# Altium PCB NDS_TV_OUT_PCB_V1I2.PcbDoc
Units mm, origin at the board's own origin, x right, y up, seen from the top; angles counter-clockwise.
Board outline 38 x 49 mm, 4 copper layers (L1, L2-GND, L3-PW, L4), stack 0.603 mm thick; 44 components, 33 nets, 151 pads, 52 vias.
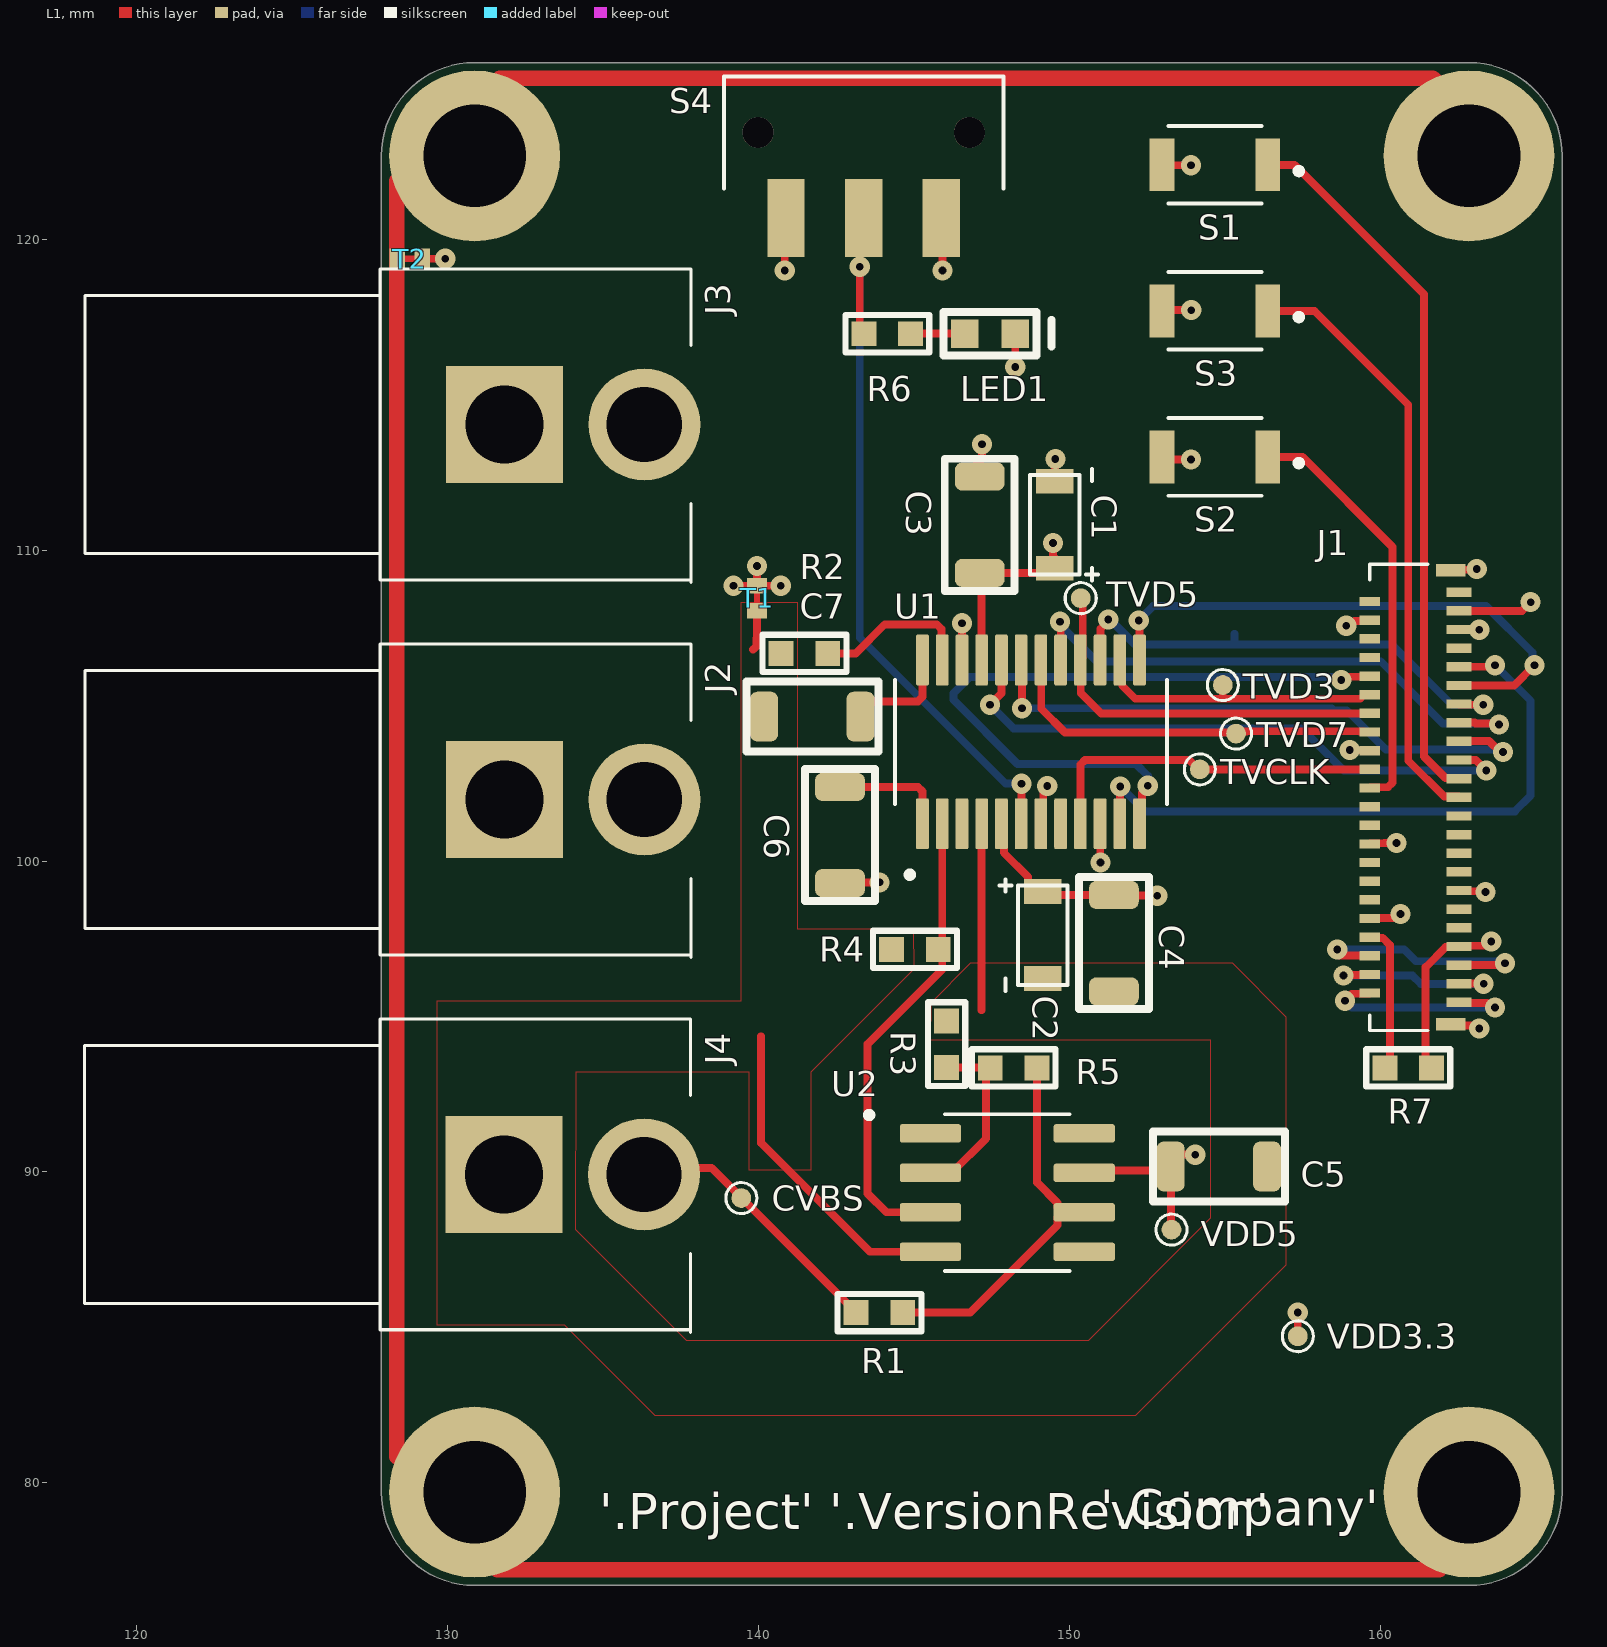
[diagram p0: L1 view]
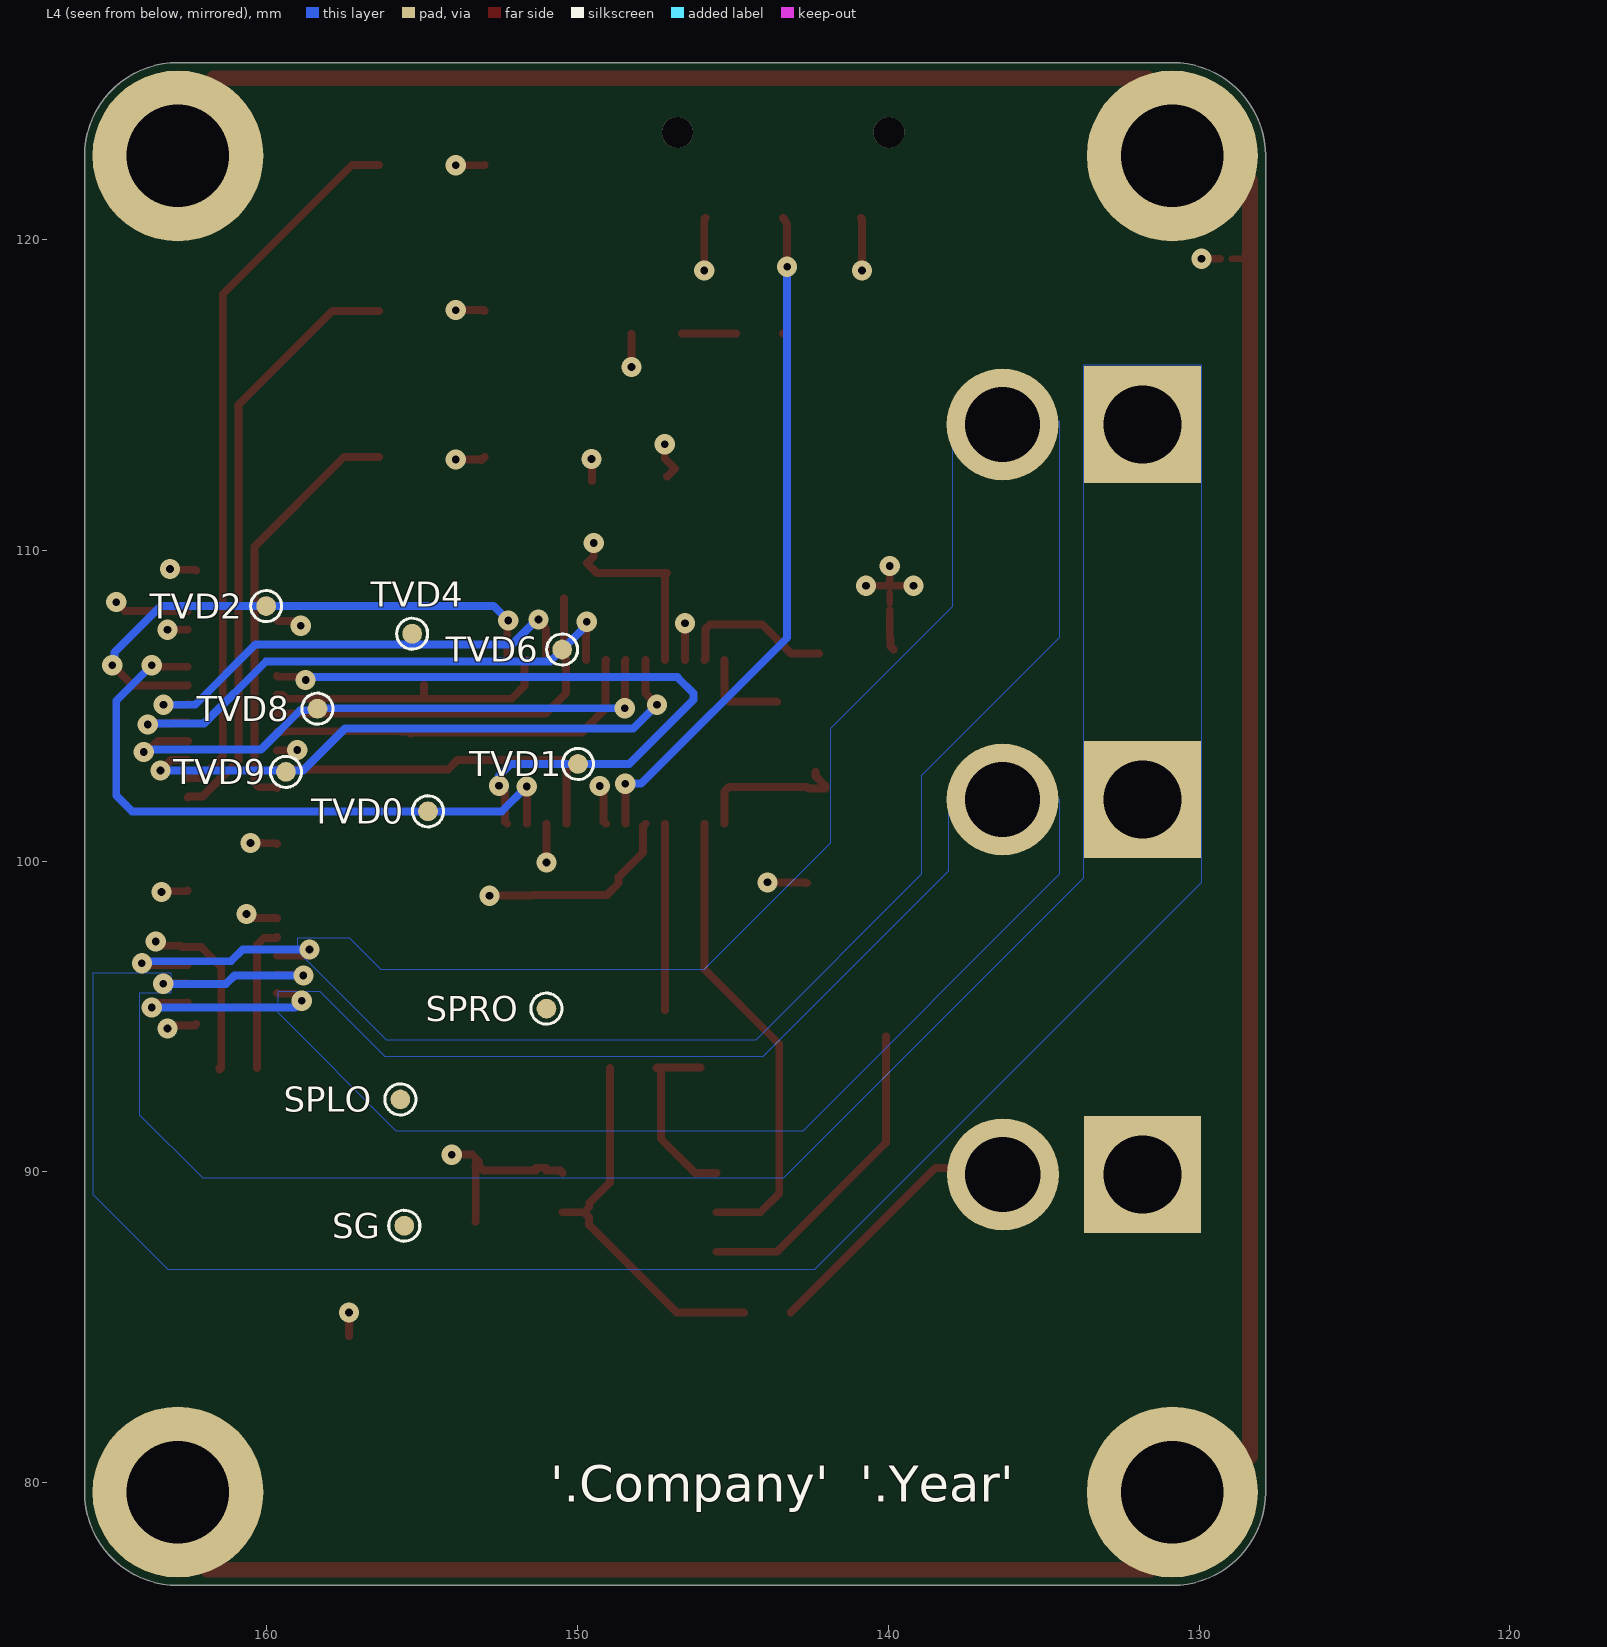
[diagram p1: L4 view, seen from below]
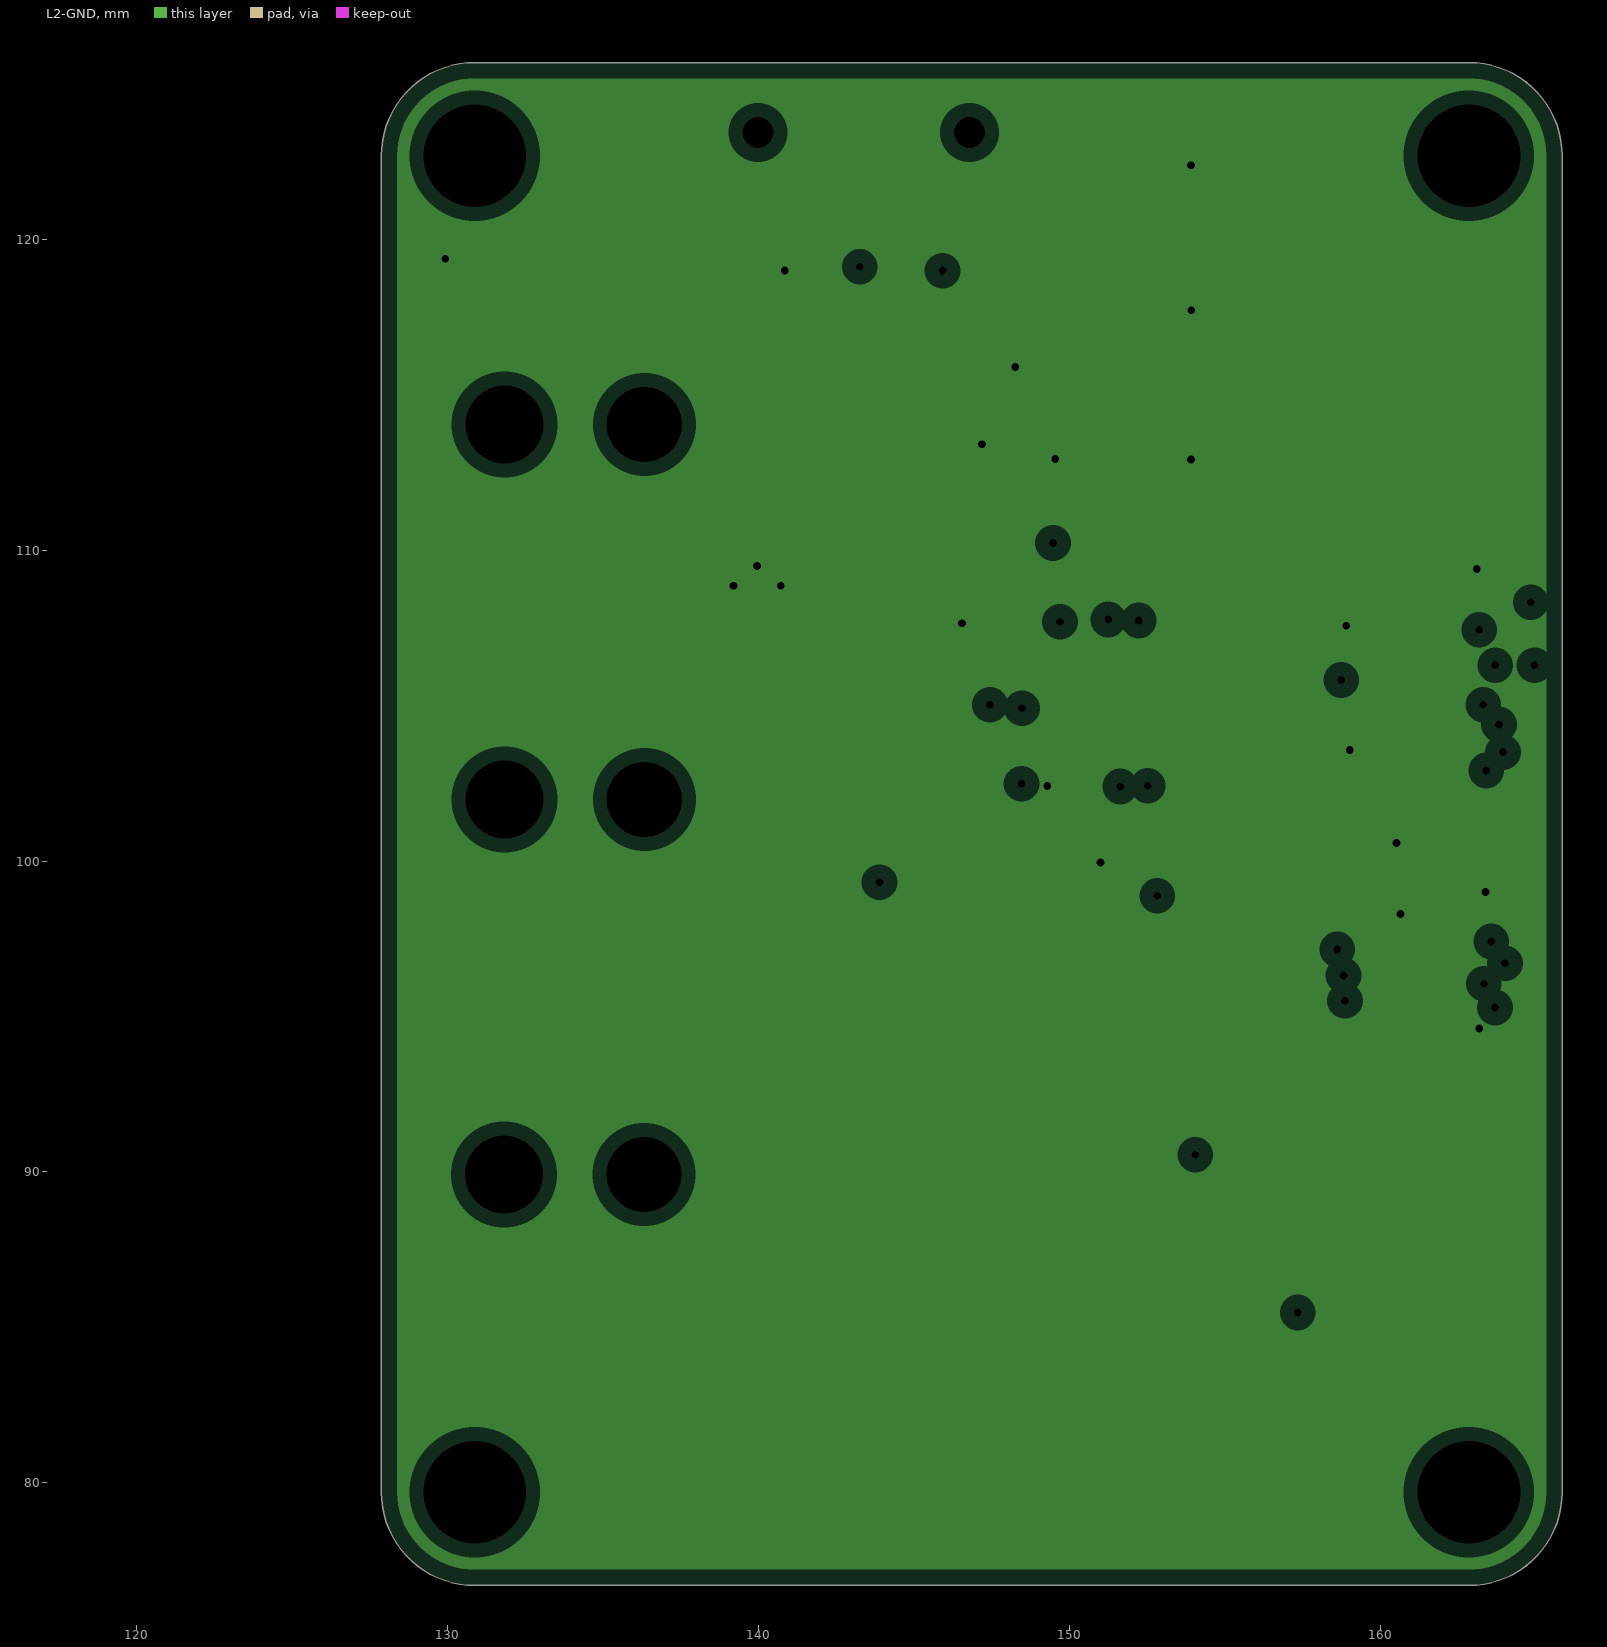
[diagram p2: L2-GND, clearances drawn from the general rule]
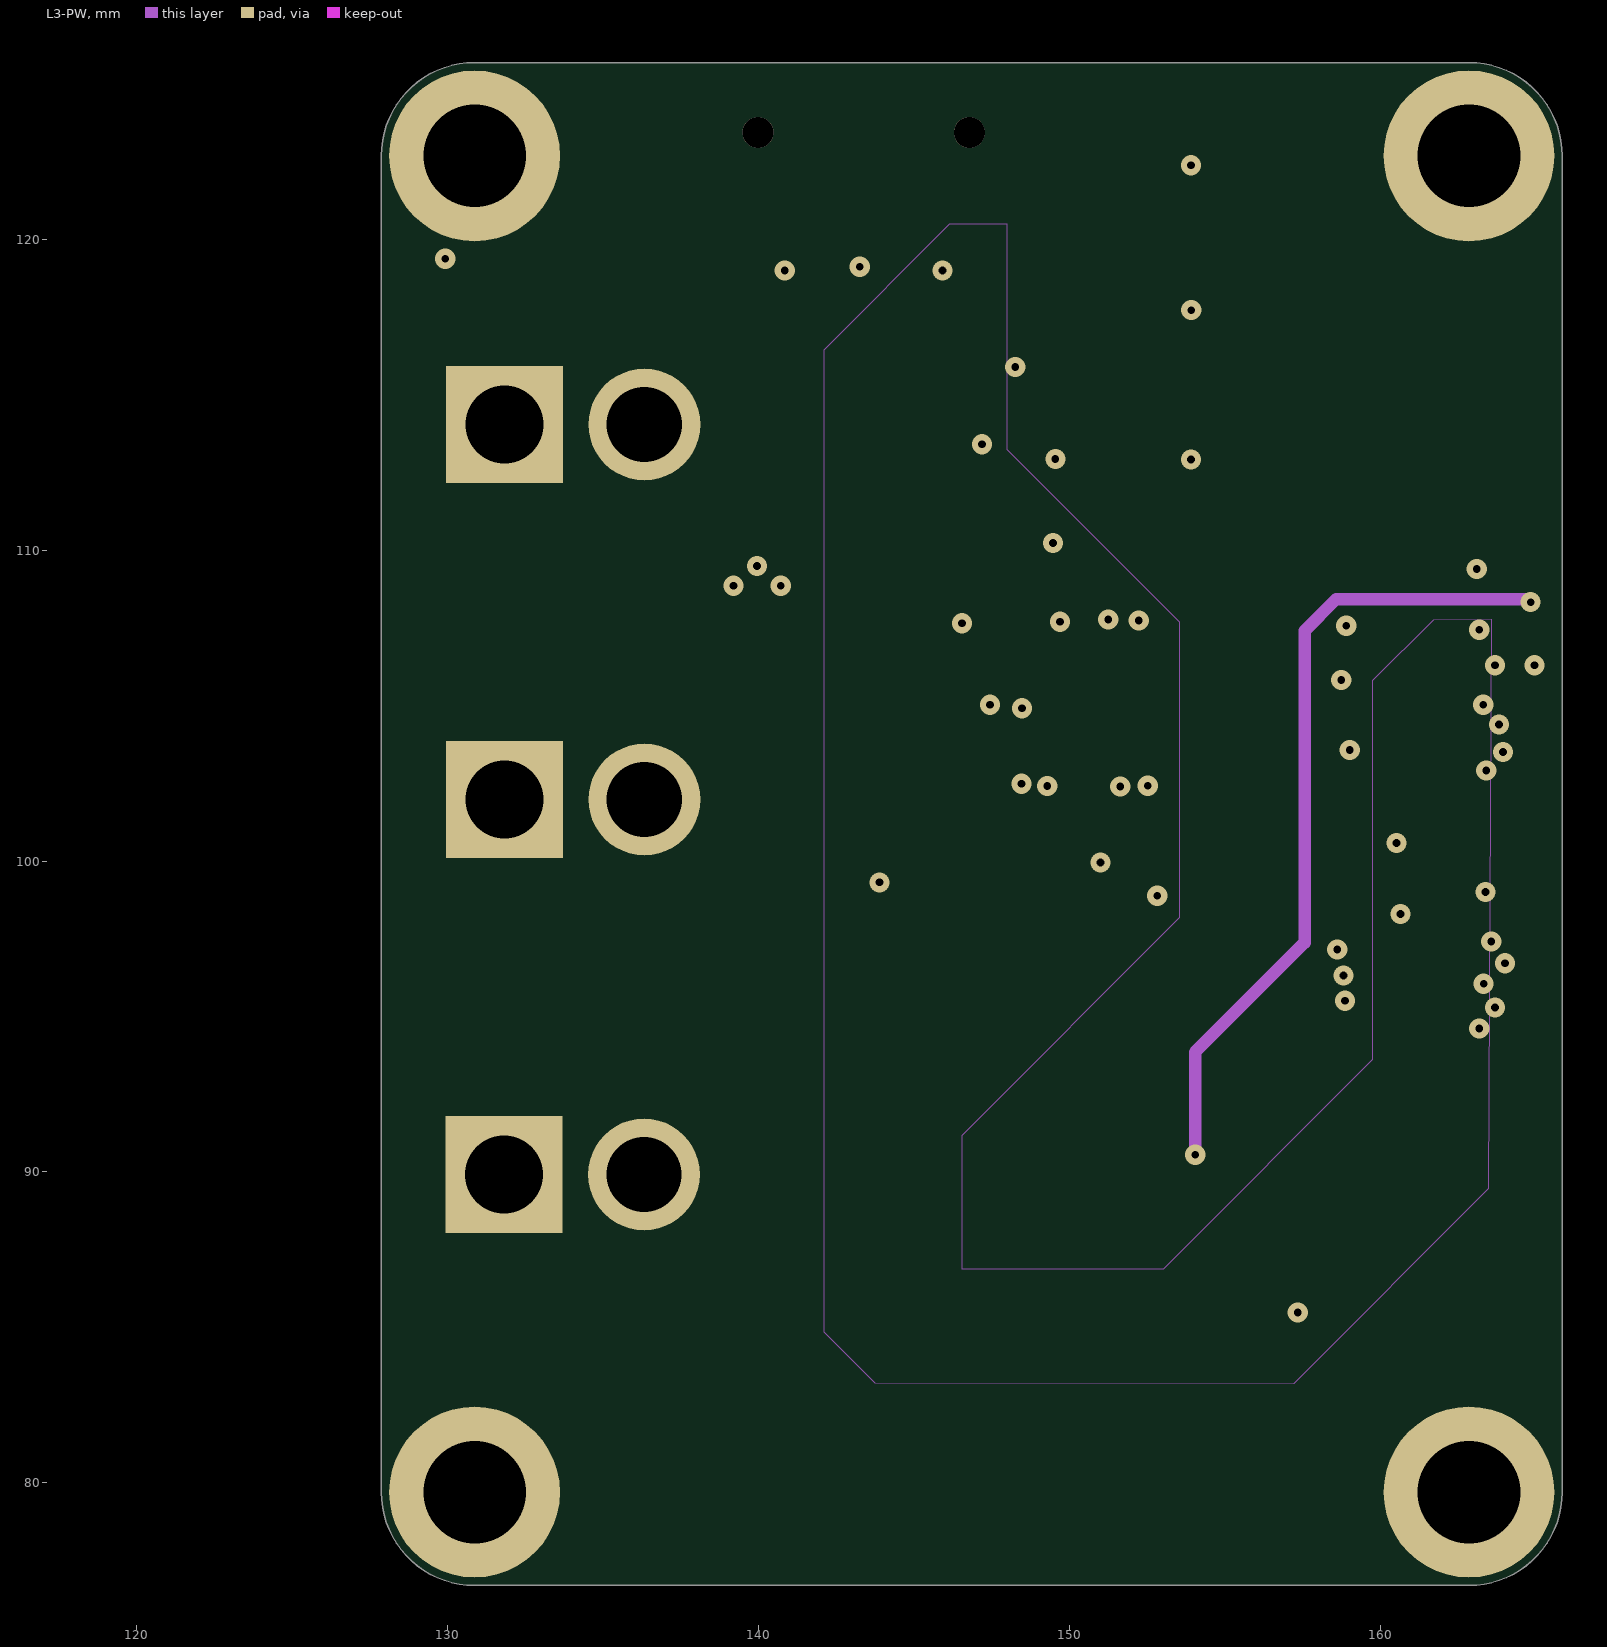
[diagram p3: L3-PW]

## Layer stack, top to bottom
Top Solder: solder mask 0.0102, Solder Resist, Dk 3.5
L1: signal copper 0.0356
Dielectric 1: prepreg 0.0711, PP-006, Dk 4.1
L2-GND: plane copper 0.035, net GND
Dielectric1: dielectric 0.32, FR-4, Dk 4.8
L3-PW: signal copper 0.035
Dielectric 2: prepreg 0.0711, PP-006, Dk 4.1
L4: signal copper 0.0356
Bottom Solder: solder mask 0.0102, Solder Resist, Dk 3.5

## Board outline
127.862,79.692 ccw(c130.862,79.692) 130.862,76.692 162.862,76.692 ccw(c162.862,79.692) 165.862,79.692 165.862,122.692 ccw(c162.862,122.692) 162.862,125.692 130.862,125.692 ccw(c130.862,122.692) 127.862,122.692

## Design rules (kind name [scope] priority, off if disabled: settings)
AssemblyTestPointUsage [All] p0: scope1count=1 scope1_0_kind=Board scope1_0_value=Board scope2count=1 scope2_0_kind=Board scope2_0_value=Board commentlength=0
AssemblyTestpoint [All] p0: scope1count=1 scope1_0_kind=Board scope1_0_value=Board scope2count=1 scope2_0_kind=Board scope2_0_value=Board commentlength=0
BoardOutlineClearance [All] p0: scope1count=1 scope1_0_kind=Board scope1_0_value=Board scope2count=1 scope2_0_kind=Board scope2_0_value=Board commentlength=0 gap=0.25
BoardOutlineClearance [All] p1: gap=0.25 ignorepadtopadclearanceinfootprint=FALSE except(0: Arc-SplitContinuation Track-SplitContinuation SMDPad-SplitContinuation THPad-SplitContinuation Via-SplitContinuation Fill-SplitContinuation Poly-SplitContinuation Region-SplitContinuation Text-SplitContinuation)
Clearance Clearance-xPP-xTP-xTT [All] p0: scope1count=1 scope1_0_kind=Board scope1_0_value=Board scope2count=1 scope2_0_kind=Board scope2_0_value=Board commentlength=0 gap=0.15
Clearance "Clearance poly Power Polygon" [All] p0 off: scope1count=1 scope1_0_kind=Layer scope1_0_value=TOP scope2count=1 scope2_0_kind=Board scope2_0_value=Board commentlength=48 gap=0.4 // Protel DXP Scope 2 Expression Was: InPolygon
Clearance "Clearance poly Power Polygon" [OnLayer('L4-PWR') vs InPolygon] p1: gap=0.4 ignorepadtopadclearanceinfootprint=FALSE
Clearance Clearance-xPP-xTP-xTT [All] p2: gap=0.15 ignorepadtopadclearanceinfootprint=FALSE
ComponentClearance [All] p0: scope1count=1 scope1_0_kind=Board scope1_0_value=Board scope2count=1 scope2_0_kind=Board scope2_0_value=Board commentlength=0 gap=0 collisioncheckmode=3
ComponentClearance [All] p1: gap=0 collisioncheckmode=3 verticalgap=0 showdistances=FALSE
DiffPairsRouting DiffPairsRoutingGBE [All] p0 off: scope1count=1 scope1_0_kind=Board scope1_0_value=Board scope2count=1 scope2_0_kind=Board scope2_0_value=Board commentlength=88 // Protel DXP Scope 1 Expression Was: InDifferentialPairClass('All Differential Pairs')
DiffPairsRouting DiffPairsRoutingGBE [InDifferentialPairClass('All Differential Pairs')] p1: maxlimit=0.22 minlimit=0.22 mostfreqgap=0.22 toplayer_minwidth=0.15 toplayer_maxwidth=0.15 toplayer_prefwidth=0.15 midlayer1_minwidth=0.15 midlayer1_maxwidth=0.15 midlayer1_prefwidth=0.15 bottomlayer_minwidth=0.15 bottomlayer_maxwidth=0.15 bottomlayer_prefwidth=0.15 maxuncoupledlength=1.25
FabricationTestPointUsage [All] p0: scope1count=1 scope1_0_kind=Board scope1_0_value=Board scope2count=1 scope2_0_kind=Board scope2_0_value=Board commentlength=0 valid=0 allowmultiple=FALSE
FabricationTestpoint [All] p0: scope1count=1 scope1_0_kind=Board scope1_0_value=Board scope2count=1 scope2_0_kind=Board scope2_0_value=Board commentlength=0 side=3 testpointundercomponent=TRUE minsize=1.016 maxsize=2.54 preferedsize=1.524 minholesize=0 maxholesize=1.016 preferedholesize=0.813 testpointgrid=0.025
FanoutControl Fanout_Default [All] p0: scope1count=1 scope1_0_kind=Board scope1_0_value=Board scope2count=1 scope2_0_kind=Board scope2_0_value=Board commentlength=30 // Fanout_Default (Default Rule)
FanoutControl Fanout_Small [All] p0 off: scope1count=1 scope1_0_kind=Board scope1_0_value=Board scope2count=1 scope2_0_kind=Board scope2_0_value=Board commentlength=84 // Protel DXP Scope 1 Expression Was: (CompPinCount < 5)   Fanout_Small (Default Rule)
FanoutControl Fanout_SOIC [All] p0 off: scope1count=1 scope1_0_kind=Board scope1_0_value=Board scope2count=1 scope2_0_kind=Board scope2_0_value=Board commentlength=71 // Protel DXP Scope 1 Expression Was: IsSOIC   Fanout_SOIC (Default Rule)
FanoutControl Fanout_LCC [All] p0 off: scope1count=1 scope1_0_kind=Board scope1_0_value=Board scope2count=1 scope2_0_kind=Board scope2_0_value=Board commentlength=69 // Protel DXP Scope 1 Expression Was: IsLCC   Fanout_LCC (Default Rule)
FanoutControl Fanout_BGA [All] p0 off: scope1count=1 scope1_0_kind=Board scope1_0_value=Board scope2count=1 scope2_0_kind=Board scope2_0_value=Board commentlength=69 // Protel DXP Scope 1 Expression Was: IsBGA   Fanout_BGA (Default Rule)
Height [All] p0: scope1count=1 scope1_0_kind=Board scope1_0_value=Board scope2count=1 scope2_0_kind=Board scope2_0_value=Board commentlength=0
Height [All] p1: minheight=0 maxheight=25 prefheight=12.5
HoleSize HoleSize-PTH [All] p0: scope1count=1 scope1_0_kind=Board scope1_0_value=Board scope2count=1 scope2_0_kind=Board scope2_0_value=Board commentlength=0 absolutevalues=TRUE maxlimit=4 minlimit=0.15 maxpercent=80.000 minpercent=20.000
HoleSize HoleSize-PTH [All] p1: absolutevalues=TRUE maxlimit=4 minlimit=0.15 maxpercent=80.000 minpercent=20.000
HoleToHoleClearance [All] p0: scope1count=1 scope1_0_kind=Board scope1_0_value=Board scope2count=1 scope2_0_kind=Board scope2_0_value=Board commentlength=0
HoleToHoleClearance [All] p1: gap=0.35 allowstackedmicrovias=TRUE
LayerPairs [All] p0: scope1count=1 scope1_0_kind=Board scope1_0_value=Board scope2count=1 scope2_0_kind=Board scope2_0_value=Board commentlength=0 enforce=TRUE
MatchedLengths MatchedLengths_USB2 [All] p0: scope1count=1 scope1_0_kind=NetClass scope1_0_value=USB2 scope2count=1 scope2_0_kind=Board scope2_0_value=Board commentlength=0 tolerance=0.127 amplitude=5.08 gap=0.508 style=90-Degree
MatchedLengths MatchedLengths_USB3 [All] p0: scope1count=1 scope1_0_kind=NetClass scope1_0_value=USB3 scope2count=1 scope2_0_kind=Board scope2_0_value=Board commentlength=0 tolerance=0.127 amplitude=5.08 gap=0.508 style=90-Degree
MatchedLengths MatchedLengths_USB-GBE [All] p0: scope1count=1 scope1_0_kind=NetClass scope1_0_value=USB-GBE scope2count=1 scope2_0_kind=Board scope2_0_value=Board commentlength=0 tolerance=0.127 amplitude=5.08 gap=0.508 style=90-Degree
MatchedLengths MatchedLengths_HDMI [All] p0: scope1count=1 scope1_0_kind=NetClass scope1_0_value=HDMI scope2count=1 scope2_0_kind=Board scope2_0_value=Board commentlength=0 tolerance=0.127 amplitude=5.08 gap=0.508 style=90-Degree
MatchedLengths MatchedLengths_GBE2 [All] p0: scope1count=1 scope1_0_kind=NetClass scope1_0_value=GBE2 scope2count=1 scope2_0_kind=Board scope2_0_value=Board commentlength=0 tolerance=0.127 amplitude=5.08 gap=0.508 style=90-Degree
MatchedLengths MatchedLengths_GBE1 [All] p0: scope1count=1 scope1_0_kind=NetClass scope1_0_value=GBE1 scope2count=1 scope2_0_kind=Board scope2_0_value=Board commentlength=0 tolerance=0.127 amplitude=5.08 gap=0.508 style=90-Degree
MatchedLengths MatchedLengths_GBE0 [All] p0: scope1count=1 scope1_0_kind=NetClass scope1_0_value=GBE0 scope2count=1 scope2_0_kind=Board scope2_0_value=Board commentlength=0 tolerance=0.127 amplitude=5.08 gap=0.508 style=90-Degree
MatchedLengths DiffPairClass [All] p0 off: scope1count=1 scope1_0_kind=Board scope1_0_value=Board scope2count=1 scope2_0_kind=Board scope2_0_value=Board commentlength=88 tolerance=0.127 amplitude=5.08 gap=0.508 style=90-Degree // Protel DXP Scope 1 Expression Was: InDifferentialPairClass('All Differential Pairs')
MatchedLengths MatchedLengths_USB_DiffPairs [All] p0 off: scope1count=1 scope1_0_kind=Board scope1_0_value=Board scope2count=1 scope2_0_kind=Board scope2_0_value=Board commentlength=140 tolerance=0.127 amplitude=5.08 gap=0.508 style=90-Degree // Protel DXP Scope 1 Expression Was: InxSignalClass('USB_CHJ1_1_DL') OR InxSignalClass('USB_CHJ1_1_RX') OR InxSignalClass('USB_CHJ1_1_TX')
MatchedLengths MatchedLengths_USB_DiffPairs_1 [All] p0 off: scope1count=1 scope1_0_kind=Board scope1_0_value=Board scope2count=1 scope2_0_kind=Board scope2_0_value=Board commentlength=140 tolerance=0.127 amplitude=5.08 gap=0.508 style=90-Degree // Protel DXP Scope 1 Expression Was: InxSignalClass('USB_CHJ1_1_DL') OR InxSignalClass('USB_CHJ1_1_RX') OR InxSignalClass('USB_CHJ1_1_TX')
MatchedLengths MatchedLengths_USB_DiffPairs_1 [InxSignalClass('USB_CHJ1_1_DL') OR InxSignalClass('USB_CHJ1_1_RX') OR InxSignalClass('USB_CHJ1_1_TX')] p1: tolerance=0.127 checknetsindiffpair=TRUE checkdiffpairvsdiffpair=FALSE checkxsignals=FALSE checkothers=FALSE
MatchedLengths MatchedLengths_USB_DiffPairs [InxSignalClass('USB_CHJ1_1_DL') OR InxSignalClass('USB_CHJ1_1_RX') OR InxSignalClass('USB_CHJ1_1_TX')] p2: tolerance=0.127 checknetsindiffpair=TRUE checkdiffpairvsdiffpair=FALSE checkxsignals=FALSE checkothers=FALSE
MatchedLengths DiffPairClass [InDifferentialPairClass('All Differential Pairs')] p3: tolerance=0.127 checknetsindiffpair=TRUE checkdiffpairvsdiffpair=FALSE checkxsignals=FALSE checkothers=FALSE
MatchedLengths MatchedLengths_GBE0 [InNetClass('GBE0')] p4: tolerance=0.127 checknetsindiffpair=FALSE checkdiffpairvsdiffpair=TRUE checkxsignals=TRUE checkothers=TRUE
MatchedLengths MatchedLengths_GBE1 [InNetClass('GBE1')] p5: tolerance=0.127 checknetsindiffpair=FALSE checkdiffpairvsdiffpair=TRUE checkxsignals=TRUE checkothers=TRUE
MatchedLengths MatchedLengths_GBE2 [InNetClass('GBE2')] p6: tolerance=0.127 checknetsindiffpair=FALSE checkdiffpairvsdiffpair=TRUE checkxsignals=TRUE checkothers=TRUE
MatchedLengths MatchedLengths_HDMI [InNetClass('HDMI')] p7: tolerance=0.127 checknetsindiffpair=FALSE checkdiffpairvsdiffpair=TRUE checkxsignals=TRUE checkothers=TRUE
MatchedLengths MatchedLengths_USB-GBE [InNetClass('USB-GBE')] p8: tolerance=0.127 checknetsindiffpair=FALSE checkdiffpairvsdiffpair=TRUE checkxsignals=TRUE checkothers=TRUE
MatchedLengths MatchedLengths_USB3 [InNetClass('USB3')] p9: tolerance=0.127 checknetsindiffpair=FALSE checkdiffpairvsdiffpair=TRUE checkxsignals=TRUE checkothers=TRUE
MatchedLengths MatchedLengths_USB2 [InNetClass('USB2')] p10: tolerance=0.127 checknetsindiffpair=FALSE checkdiffpairvsdiffpair=TRUE checkxsignals=TRUE checkothers=TRUE
MinimumAnnularRing "Minimum IAR <=0.45mm" [All] p0 off: scope1count=1 scope1_0_kind=Board scope1_0_value=Board scope2count=1 scope2_0_kind=Board scope2_0_value=Board commentlength=209 minimumring=0.175 // Protel DXP Scope 1 Expression Was: ((ObjectKind = 'Pad') OR (ObjectKind = 'Via')) And (Layer = 'MultiLayer') And (HoleDiameter <= AsMM(0.45))   minimum inner annular ring for pads <= 0.45mm finished hole size
MinimumAnnularRing "Minimum IAR  >0.45mm" [All] p0 off: scope1count=1 scope1_0_kind=Board scope1_0_value=Board scope2count=1 scope2_0_kind=Board scope2_0_value=Board commentlength=207 minimumring=0.175 // Protel DXP Scope 1 Expression Was: ((ObjectKind = 'Pad') OR (ObjectKind = 'Via')) And (Layer = 'MultiLayer') And (HoleDiameter > AsMM(0.45))   minimum inner annular ring for pads > 0.45mm finished hole size
MinimumAnnularRing "Minimum IAR  >0.45mm" [((ObjectKind = 'Pad') OR (ObjectKind = 'Via')) And (Layer = 'MultiLayer') And (HoleDiameter > AsMM(0.45))] p1: minimumring=0.175 // minimum inner annular ring for pads > 0.45mm finished hole size
MinimumAnnularRing "Minimum IAR <=0.45mm" [((ObjectKind = 'Pad') OR (ObjectKind = 'Via')) And (Layer = 'MultiLayer') And (HoleDiameter <= AsMM(0.45))] p2: minimumring=0.175 // minimum inner annular ring for pads <= 0.45mm finished hole size
MinimumSolderMaskSliver [All] p0: scope1count=1 scope1_0_kind=Board scope1_0_value=Board scope2count=1 scope2_0_kind=Board scope2_0_value=Board commentlength=0
MinimumSolderMaskSliver [All] p1: minsoldermaskwidth=0.08
NetAntennae [All] p0: scope1count=1 scope1_0_kind=Board scope1_0_value=Board scope2count=1 scope2_0_kind=Board scope2_0_value=Board commentlength=0
PasteMaskExpansion [All] p0: scope1count=1 scope1_0_kind=Board scope1_0_value=Board scope2count=1 scope2_0_kind=Board scope2_0_value=Board commentlength=0 expansion=0
PlaneClearance PlaneClearance-IPI [All] p0: scope1count=1 scope1_0_kind=Board scope1_0_value=Board scope2count=1 scope2_0_kind=Board scope2_0_value=Board commentlength=0 clearance=0.45
PlaneClearance PlaneClearance-IPI [All] p1: clearance=0.45
PlaneConnect [All] p0: scope1count=1 scope1_0_kind=Board scope1_0_value=Board scope2count=1 scope2_0_kind=Board scope2_0_value=Board commentlength=0 planeconnectstyle=Relief reliefexpansion=0.2 reliefentries=4 reliefconductorwidth=0.25 reliefairgap=0.2
PlaneConnect PlaneConnect_VIA [All] p0 off: scope1count=1 scope1_0_kind=Board scope1_0_value=Board scope2count=1 scope2_0_kind=Board scope2_0_value=Board commentlength=44 planeconnectstyle=Direct reliefexpansion=0.175 reliefentries=4 reliefconductorwidth=0.2 reliefairgap=0.2 // Protel DXP Scope 1 Expression Was: IsVia
PlaneConnect PlaneConnect_PWR [All] p0: scope1count=1 scope1_0_kind=NetClass scope1_0_value=PWR scope2count=1 scope2_0_kind=Board scope2_0_value=Board commentlength=0 planeconnectstyle=Direct reliefexpansion=0.175 reliefentries=2 reliefconductorwidth=0.2 reliefairgap=0.2
PlaneConnect PlaneConnect_PWR [InNetClass('PWR')] p1: planeconnectstyle=Direct reliefexpansion=0.175 reliefentries=2 reliefconductorwidth=0.2 reliefairgap=0.2
PlaneConnect PlaneConnect_VIA [IsVia] p2: planeconnectstyle=Direct reliefexpansion=0.175 reliefentries=4 reliefconductorwidth=0.2 reliefairgap=0.2
PlaneConnect [All] p3: planeconnectstyle=Relief reliefexpansion=0.2 reliefentries=4 reliefconductorwidth=0.25 reliefairgap=0.2
PolygonConnect PolygonConnect_VIA_1 [All] p0: scope1count=1 scope1_0_kind=Board scope1_0_value=Board scope2count=1 scope2_0_kind=Board scope2_0_value=Board commentlength=0 connectstyle=Direct reliefconductorwidth=0.2 reliefentries=4 polygonreliefangle="90 Angle"
PolygonConnect PolygonConnect_SMD [All] p0 off: scope1count=1 scope1_0_kind=Board scope1_0_value=Board scope2count=1 scope2_0_kind=Board scope2_0_value=Board commentlength=84 connectstyle=Direct reliefconductorwidth=0.2 reliefentries=4 polygonreliefangle="90 Angle" // Protel DXP Scope 1 Expression Was: Not HasFootprint('NET_TIE') and InNet('AGND')
PolygonConnect [All] p0: scope1count=1 scope1_0_kind=Board scope1_0_value=Board scope2count=1 scope2_0_kind=Board scope2_0_value=Board commentlength=0 connectstyle=Relief reliefconductorwidth=0.25 reliefentries=4 polygonreliefangle="90 Angle"
PolygonConnect PolygonConnect_VIA [All] p0: scope1count=1 scope1_0_kind=Footprint scope1_0_value=NET_TIE scope2count=1 scope2_0_kind=Board scope2_0_value=Board commentlength=0 connectstyle=Direct reliefconductorwidth=0.2 reliefentries=4 polygonreliefangle="90 Angle"
PolygonConnect PolygonConnect_VIA [HasFootprint('NET_TIE')] p1: connectstyle=Direct reliefconductorwidth=0.2 reliefentries=4 polygonreliefangle="90 Angle" airgapwidth=0.2
PolygonConnect PolygonConnect_SMD [Not HasFootprint('NET_TIE') and InNet('AGND')] p2: thpad.connectstyle=Direct thpad.reliefconductorwidth=0.2 thpad.reliefentries=4 thpad.polygonreliefangle="90 Angle" thpad.airgapwidth=0.2 smdpad.connectstyle=Relief smdpad.reliefconductorwidth=0.2 smdpad.reliefentries=4 smdpad.polygonreliefangle="90 Angle" smdpad.airgapwidth=0.2 via.connectstyle=Direct via.reliefconductorwidth=0.2 via.reliefentries=4 via.polygonreliefangle="90 Angle" via.airgapwidth=0.2
PolygonConnect PolygonConnect_VIA_1 [All] p3: connectstyle=Direct reliefconductorwidth=0.2 reliefentries=4 polygonreliefangle="90 Angle" airgapwidth=0.2
PolygonConnect [All] p4: connectstyle=Relief reliefconductorwidth=0.25 reliefentries=4 polygonreliefangle="90 Angle" airgapwidth=0.2
RoutingCorners [All] p0: scope1count=1 scope1_0_kind=Board scope1_0_value=Board scope2count=1 scope2_0_kind=Board scope2_0_value=Board commentlength=0 cornerstyle=45-Degree minsetback=2.5 maxsetback=2.5
RoutingCorners [All] p1: cornerstyle=45-Degree minsetback=2.5 maxsetback=2.5
RoutingLayers [All] p0: scope1count=1 scope1_0_kind=Board scope1_0_value=Board scope2count=1 scope2_0_kind=Board scope2_0_value=Board commentlength=0 top layer=Automatic mid layer 1=Automatic bottom layer=Automatic
RoutingPriority [All] p0: scope1count=1 scope1_0_kind=Board scope1_0_value=Board scope2count=1 scope2_0_kind=Board scope2_0_value=Board commentlength=0
RoutingTopology [All] p0: scope1count=1 scope1_0_kind=Board scope1_0_value=Board scope2count=1 scope2_0_kind=Board scope2_0_value=Board commentlength=0 topology=Shortest
RoutingVias "RoutingVias <= 0.45mm" [All] p0 off: scope1count=1 scope1_0_kind=Board scope1_0_value=Board scope2count=1 scope2_0_kind=Board scope2_0_value=Board commentlength=120 holewidth=0.2 width=0.55 viastyle="Through Hole" minholewidth=0.15 minwidth=0.5 maxholewidth=0.45 maxwidth=0.8 // Protel DXP Scope 1 Expression Was: (ObjectKind = 'Via') And (HoleDiameter <= AsMM(0.45))   finishet hole size <= 0.45mm
RoutingVias "RoutingVias > 0.45mm" [All] p0 off: scope1count=1 scope1_0_kind=Board scope1_0_value=Board scope2count=1 scope2_0_kind=Board scope2_0_value=Board commentlength=118 holewidth=0.5 width=0.85 viastyle="Through Hole" minholewidth=0.5 minwidth=0.85 maxholewidth=0.9 maxwidth=1.25 // Protel DXP Scope 1 Expression Was: (ObjectKind = 'Via') And (HoleDiameter > AsMM(0.45))   finishet hole size > 0.45mm
RoutingVias "RoutingVias > 0.45mm" [(ObjectKind = 'Via') And (HoleDiameter > AsMM(0.45))] p1: holewidth=0.5 width=0.85 viastyle="Through Hole" minholewidth=0.5 minwidth=0.85 maxholewidth=0.9 maxwidth=1.25 // finishet hole size > 0.45mm
RoutingVias "RoutingVias <= 0.45mm" [(ObjectKind = 'Via') And (HoleDiameter <= AsMM(0.45))] p2: holewidth=0.2 width=0.55 viastyle="Through Hole" minholewidth=0.15 minwidth=0.5 maxholewidth=0.45 maxwidth=0.8 // finishet hole size <= 0.45mm
ShortCircuit [All] p0: scope1count=1 scope1_0_kind=Board scope1_0_value=Board scope2count=1 scope2_0_kind=Board scope2_0_value=Board commentlength=0 allowed=FALSE
SilkToBoardRegionClearance [All] p0: scope1count=1 scope1_0_kind=Board scope1_0_value=Board scope2count=1 scope2_0_kind=Board scope2_0_value=Board commentlength=0
SilkToSilkClearance [All] p0: scope1count=1 scope1_0_kind=Board scope1_0_value=Board scope2count=1 scope2_0_kind=Board scope2_0_value=Board commentlength=0
SilkToSilkClearance [All] p1: silktosilkclearance=0.1
SilkToSolderMaskClearance SilkscreenOverComponentPads [All] p0 off: scope1count=1 scope1_0_kind=Board scope1_0_value=Board scope2count=1 scope2_0_kind=Board scope2_0_value=Board commentlength=44 // Protel DXP Scope 1 Expression Was: IsPad
SilkToSolderMaskClearance SilkscreenOverComponentPads [IsPad] p1: minsilkscreentomaskgap=0.1 clearancetoexposedcopper=TRUE
SolderMaskExpansion [All] p0: scope1count=1 scope1_0_kind=Board scope1_0_value=Board scope2count=1 scope2_0_kind=Board scope2_0_value=Board commentlength=0 expansion=0
SolderMaskExpansion [All] p1: expansion=0 istentingtop=FALSE
UnRoutedNet [All] p0: scope1count=1 scope1_0_kind=Board scope1_0_value=Board scope2count=1 scope2_0_kind=Board scope2_0_value=Board commentlength=0
UnRoutedNet [All] p1: checkbadconnections=TRUE
UnpouredPolygon [All] p0: scope1count=1 scope1_0_kind=Board scope1_0_value=Board scope2count=1 scope2_0_kind=Board scope2_0_value=Board commentlength=0
Width Width-Power [All] p0: scope1count=1 scope1_0_kind=NetClass scope1_0_value=PWR scope2count=1 scope2_0_kind=Board scope2_0_value=Board commentlength=0 maxlimit=5 minlimit=0.2 preferedwidth=0.25
Width Width-GigaE [All] p0: scope1count=1 scope1_0_kind=Board scope1_0_value=Board scope2count=1 scope2_0_kind=Board scope2_0_value=Board commentlength=0 maxlimit=0.15 minlimit=0.15 preferedwidth=0.15
Width Width-xTW [All] p0: scope1count=1 scope1_0_kind=Board scope1_0_value=Board scope2count=1 scope2_0_kind=Board scope2_0_value=Board commentlength=0 maxlimit=5 minlimit=0.125 preferedwidth=0.15
Width Width-xTW [All] p1: maxlimit=5 minlimit=0.125 preferedwidth=0.15
Width Width-GigaE [All] p2: maxlimit=0.15 minlimit=0.15 preferedwidth=0.15
Width Width-Power [InNetClass('PWR')] p3: maxlimit=5 minlimit=0.2 preferedwidth=0.25
18 further rules are at their usual default settings.

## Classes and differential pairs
component class "[05] - BUTTONS AND SWITCHES": LED1 R7 S1 S2 S3 S4
component class "[04] - CONNECTORS": J1 J2 J3 J4 SG SPLO SPRO T1 T2 TVCLK TVD0 TVD1 TVD2 TVD3 TVD4 TVD5 TVD6 TVD7 TVD8 TVD9 VDD3.3 VDD5
component class "[03] - DAC": C1 C2 C3 C4 C7 CVBS R3 U1 U2

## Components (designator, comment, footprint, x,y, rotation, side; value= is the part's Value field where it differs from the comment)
C1 "10uF" C1206T 150.33,109.223 r90 top
C2 "10uF" C1206T 148.349,99.215 r270 top
C3 "0.1uF" C1206 147.117,110.82 r270 top
C4 "0.1uF" C1206 151.435,97.358 r90 top
C5 "0.1uF" C1206 154.813,90.17 r180 top
C6 "0.1uF" C1206 142.621,100.838 r90 top
C7 "0.1uF" C1206 141.732,104.648 r0 top
CVBS "TP_25MILC" TP_25C 139.446,89.154 r90 top
J1 "4-2328724-5" 423287245 161.106,102.051 r90 top
J2 "KLPX-0848A-2-W" KLPX0848A2W 131.826,101.981 r0 top
J3 "KLPX-0848A-2-R" KLPX0848A2R 131.826,114.046 r0 top
J4 "KLPX-0848A-2-Y" KLPX0848A2Y 131.815,89.916 r0 top
LED1 "APTD1608LZGCK" RESC0603X55N 147.447,116.967 r180 top
R1 "75R" R0603 143.891,85.471 r180 top
R2 "DNP" R0603 141.478,106.68 r0 top
R3 "430R" R0603 146.05,94.107 r270 top
R4 "DNP" R0603 145.034,97.155 r0 top
R5 "1K" R0603 148.209,93.345 r0 top
R6 "320R" R0603 144.145,116.967 r180 top
R7 "1K" R0603 160.909,93.345 r0 top
S1 "B3U-1000P" SW_B3U-1000P 154.686,122.404 r180 top
S2 "B3U-1000P" SW_B3U-1000P 154.686,113.006 r180 top
S3 "B3U-1000P" SW_B3U-1000P 154.686,117.705 r180 top
S4 "JS102011SAQN" SW_JS102011SAQN 143.383,123.444 r180 top
SG "TP_25MILC" TP_25C 155.575,88.265 r90 bottom
SPLO "TP_25MILC" TP_25C 155.702,92.329 r90 bottom
SPRO "TP_25MILC" TP_25C 151.003,95.25 r90 bottom
T1 "NET TIE" NET_TIE 139.954,108.458 r90 top net-tie
T2 "NET TIE" NET_TIE 128.778,119.38 r0 top net-tie
TVCLK "TP_25MILC" TP_25C 154.2,102.951 r90 top
TVD0 "TP_25MILC" TP_25C 154.813,101.6 r90 bottom
TVD1 "TP_25MILC" TP_25C 149.987,103.124 r90 bottom
TVD2 "TP_25MILC" TP_25C 160.02,108.204 r90 bottom
TVD3 "TP_25MILC" TP_25C 154.94,105.664 r90 top
TVD4 "TP_25MILC" TP_25C 155.321,107.315 r90 bottom
TVD5 "TP_25MILC" TP_25C 150.368,108.458 r90 top
TVD6 "TP_25MILC" TP_25C 150.495,106.807 r90 bottom
TVD7 "TP_25MILC" TP_25C 155.366,104.1 r90 top
TVD8 "TP_25MILC" TP_25C 158.369,104.902 r90 bottom
TVD9 "" TP_25C 159.385,102.87 r90 bottom
U1 "MAX5184BEEG+" SOP63P602X175-24N 148.768,103.835 r90 top
U2 "MAX4414ESA+" SOIC127P600X175-8N 148.006,89.332 r0 top
VDD3.3 "TP_25MILC" TP_25C 157.353,84.709 r90 top
VDD5 "TP_25MILC" TP_25C 153.289,88.138 r90 top

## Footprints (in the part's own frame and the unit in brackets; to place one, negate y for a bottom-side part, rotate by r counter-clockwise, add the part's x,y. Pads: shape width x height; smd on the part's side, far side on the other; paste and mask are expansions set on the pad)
423287245 [mm]
  rect 0.3x0.8 smd: 1(-6.6,-1.438) 3(-6,-1.438) 5(-5.4,-1.438) 7(-4.8,-1.438) 9(-4.2,-1.438) 11(-3.6,-1.438) 13(-3,-1.438) 15(-2.4,-1.438) 17(-1.8,-1.438) 19(-1.2,-1.438) 21(-0.6,-1.438) 23(0,-1.438) 25(0.6,-1.438) 27(1.2,-1.438) 29(1.8,-1.438) 31(2.4,-1.438) 33(3,-1.438) 35(3.6,-1.438) 37(4.2,-1.438) 39(4.8,-1.438) 41(5.4,-1.438) 43(6,-1.438) 45(6.6,-1.438)
  rect 0.3x0.65 smd: 2(-6.3,1.438) 4(-5.7,1.438) 6(-5.1,1.438) 8(-4.5,1.438) 10(-3.9,1.438) 12(-3.3,1.438) 14(-2.7,1.438) 16(-2.1,1.438) 18(-1.5,1.438) 20(-0.9,1.438) 22(-0.3,1.438) 24(0.3,1.438) 26(0.9,1.438) 28(1.5,1.438) 30(2.1,1.438) 32(2.7,1.438) 34(3.3,1.438) 36(3.9,1.438) 38(4.5,1.438) 40(5.1,1.438) 42(5.7,1.438) 44(6.3,1.438)
  rect 0.4x0.95 smd: 46(-7.3,-1.163) 47(7.3,-1.163)
  silkscreen extent -7.5,-0.44 7.5,1.44
C1206 [mm]
  rrect50% 0.9x1.6 smd: 1(-1.55,0) 2(1.55,0)
  silkscreen extent -2.12,-1.12 2.12,1.12
C1206T [mm]
  rect 0.8x1.2 smd: 1(0.2,0.8) 2(3,0.8)
  silkscreen extent -0.2,-0.6 3.4,1.6
KLPX0848A2R [mm]
  rect 3.765x3.765 hole 2.51: 1(0,0)
  round 3.6 hole 2.42: 2(4.5,0)
  silkscreen extent -13.5,-5.08 6,5
KLPX0848A2W [mm]
  rect 3.765x3.765 hole 2.51: 1(0,0)
  round 3.6 hole 2.42: 2(4.5,0)
  silkscreen extent -13.5,-5.08 6,5
KLPX0848A2Y [mm]
  rect 3.765x3.765 hole 2.51: 1(0,0)
  round 3.6 hole 2.42: 2(4.5,0)
  silkscreen extent -13.5,-5.08 6,5
NET_TIE [mm]
  rect 0.5x0.65 smd paste-1 mask+0: 1(-0.4,0) 2(0.4,0)
  L1 lines w0.2: -0.175,0 0.175,0
R0603 [mm]
  rect 0.8x0.8 smd: 1(-0.75,0) 2(0.75,0)
  silkscreen extent -1.35,-0.6 1.35,0.6
RESC0603X55N [mm]
  rect 0.89x0.93 smd: 1(-0.814,0) 2(0.814,0)
  silkscreen extent -1.97,-0.7 1.5,0.7
SOIC127P600X175-8N [mm]
  rrect25% 1.97x0.59 smd: 1(-2.475,1.905) 2(-2.475,0.635) 3(-2.475,-0.635) 4(-2.475,-1.905) 5(2.475,-1.905) 6(2.475,-0.635) 7(2.475,0.635) 8(2.475,1.905)
  silkscreen extent -4.54,-2.52 2,2.59
SOP63P602X175-24N [mm]
  rrect25% 1.64x0.41 smd: 1(-2.635,3.492) 2(-2.635,2.857) 3(-2.635,2.222) 4(-2.635,1.587) 5(-2.635,0.952) 6(-2.635,0.317) 7(-2.635,-0.318) 8(-2.635,-0.953) 9(-2.635,-1.588) 10(-2.635,-2.222) 11(-2.635,-2.857) 12(-2.635,-3.492) 13(2.635,-3.492) 14(2.635,-2.857) 15(2.635,-2.222) 16(2.635,-1.587) 17(2.635,-0.952) 18(2.635,-0.317) 19(2.635,0.318) 20(2.635,0.953) 21(2.635,1.588) 22(2.635,2.222) 23(2.635,2.857) 24(2.635,3.492)
  silkscreen extent -4.37,-4.37 1.99,4.37
SW_B3U-1000P [mm]
  rect 0.8x1.7 smd: 1(-1.7,0) 2(1.7,0)
  silkscreen extent -2.8,-1.25 1.5,1.25
SW_JS102011SAQN [mm]
  rect 1.2x2.5 smd: 1(-2.5,2.75) 2(0,2.75) 3(2.5,2.75)
  round 1 hole 1 unplated: ""(-3.4,0) ""(3.4,0)
  silkscreen extent -4.5,-1.8 4.5,1.8
TP_25C [mm]
  round 0.635 smd paste-0.635 mask+0: 1(0,0)
  silkscreen extent -0.5,-0.5 0.5,0.5

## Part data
C1 C2: library part T491A106K010AT, "CAPACITOR, CASE A, 10UF, 10V; Product Range:KEMET - T491 Series; Capacitance:10µF; Capacitance Tolerance:± 10%; Voltage Rating:10V; Capacitor Case Style:1206 [3216 Metric]; Manufacturer Size Code:A; Operating Temperature Max:125°C; ;RoHS Compliant: Yes"
C3 C4 C5 C6 C7: library part GRM319R71H104KA01D, "MURATA - GRM319R71H104KA01D - COND, CERÁ MULT, X7R, 100NF, 50V, 1206"
CVBS SG SPLO SPRO TVCLK TVD0 TVD1 TVD2 TVD3 TVD4 TVD5 TVD6 TVD7 TVD8 VDD3.3 VDD5: "Test Point 25mil"
J1: "FPC Connector; 0.3mm pitch front flip FPC; 45pos"
J2 J3 J4: "Conn RCA F 2 POS 4.5mm Solder RA Thru-Hole 2 Terminal 1 Port"
LED1: "LED GREEN CLEAR 0603 SMD"
R1: library part CRCW060375R0FKEA, "VISHAY - CRCW060375R0FKEA - RES, 75R, 1%, 0.1W, 0603, THICK FILM"
R2 R4: library part R0603
R3: library part MCWF06R4300BTL, "Res, 430R, 0.1%, 0.1W, 0603, Thin Film"
R5 R7: library part ESR03EZPF1001, "ROHM - ESR03EZPF1001 - SMD Chip Resistor, Anti-Surge, 0603 [1608 Metric], 1 kohm, ESR Series, 150 V, Thick Film, 250 mW"
R6: library part RT0603DRE07320RL, "High Precision-High Stability Chip Resistor Thin Film 0603 320Ohm 0.5% Paper T/R"
S1 S2 S3: "SWITCH TACTILE SPST-NO 0.05A 12V"
S4: "Slide Switch, JS Series, SPDT, Right Angle, SMD, 100 mA ;RoHS Compliant: Yes"
T1 T2: library part NET_TIE
TVD9: library part TP_25MILC, "Test Point 25mil"
U1: "DAC 1-CH Current Steering 10-bit 24-Pin QSOP"
U2: "IC OPAMP VFB 400MHZ RRO 8SOIC"

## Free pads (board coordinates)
  round 5.5 hole 3.3: 3(130.862,79.692) 3(130.862,122.692) 3(162.862,79.692) 3(162.862,122.692)

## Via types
v1: diameter 0.65, hole 0.25, L1 to L4, tented both sides, 52 vias

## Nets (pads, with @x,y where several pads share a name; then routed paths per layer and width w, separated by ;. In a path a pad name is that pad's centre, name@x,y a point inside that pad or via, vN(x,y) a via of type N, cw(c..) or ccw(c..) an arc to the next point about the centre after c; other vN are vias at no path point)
+3.3V: C1.1 C2.1 C3.2 C4.2 C6.1 J1.41 S4.1 U1.5 U1.21 VDD3.3.1 | length 17.3
  L1 w0.254: C6.1 142.647,99.314 v1(143.891,99.314) ; S4.1 145.923,120.654 v1(145.923,118.999) ; U1.21 147.181,109.206 C3.2 149.377,109.27 149.694,109.586 149.479,109.801 v1(149.479,110.236) ; U1.5 147.894,101.122 147.894,100.27 148.676,99.488 148.676,99.288 149.056,98.908 C4.2 151.448,98.895 152.819,98.895 v1(152.832,98.882) ; VDD3.3.1 v1(157.353,85.471) ; J1.41 162.553,107.442 v1(163.195,107.442)
+5V: C5.2 J1.43 U2.7 VDD5.1 | length 34.5
  L1 w0.254: U2.7 150.557,90.043 U2.7@151.009,90.043 ; U2.7@151.009,90.13 U2.7@151.334,90.13 ; U2.7@151.334,90.043 153.023,90.043 C5.2@153.233,90.252 ; C5.2 C5.2@153.276,90.157 ; C5.2@153.282,90.189 153.289,90.196 C5.2@153.276,90.209 ; VDD5.1@153.289,88.392 153.276,88.405 C5.2@153.276,90.157 ; v1(154.051,90.551) 153.39,90.551 153.162,90.323 C5.2@153.233,90.252 ; J1.43 164.566,108.051 v1(164.846,108.331) ; C5.2@153.233,90.252 C5.2@153.276,90.209 ; C5.2@153.233,90.252 153.276,90.296 C5.2@153.276,90.209 ; C5.2@153.276,90.157 C5.2@153.276,90.209
  L3-PW w0.4: v1(154.051,90.551) 154.051,93.853 157.571,97.373 157.571,107.406 158.592,108.427 164.683,108.427 164.778,108.331 v1(164.846,108.331)
AGND: C2.2 C4.1 C5.1 C7.1 J4.1 R2.1 R3.1 R4.1 T1.1 U1.4 U2.4 | length 17.6
  L1 w0.254: 139.827,106.807 139.932,106.912 139.932,107.166 139.954,107.188 T1.1 ; 140.081,94.361 140.081,90.932 143.586,87.427 U2.4 ; 147.181,95.199 U1.4
GND: C1.2 C3.1 J1.10 J1.13 J1.18 J1.28 J1.42 J1.46 J1.47 LED1.1 S1.2 S2.2 S3.2 S4.3 T1.2 T2.2 U1.7 U1.10 U1.22 | length 20.3
  L1 w0.254: T2.2@129.33,119.38 v1(129.921,119.38) ; v1(139.192,108.858) T1.2 ; v1(139.954,109.493) T1.2 ; v1(140.716,108.858) T1.2 ; v1(140.843,118.999) 140.843,120.654 S4.3 ; U1.22 146.552,106.476 146.547,106.481 v1(146.547,107.654) ; C3.1 146.863,112.624 147.193,112.953 v1(147.193,113.411) ; v1(148.261,115.899) LED1.1 ; U1.7 149.164,101.278 149.164,102.251 149.289,102.376 v1(149.289,102.415) ; C1.2 149.534,112.226 149.534,112.919 v1(149.552,112.937) ; U1.10 150.997,101.194 150.997,99.955 v1(151.003,99.949) ; S2.2 153.089,112.903 153.123,112.937 153.139,112.921 v1(153.919,112.921) ; S3.2 153.009,117.727 v1(153.923,117.727) ; S1.2 153.001,122.389 v1(153.919,122.389) ; v1(158.91,107.569) 159.017,107.569 159.176,107.728 159.645,107.728 J1.42 ; v1(159.022,103.576) 159.035,103.563 159.655,103.563 J1.28 ; J1.10 159.688,98.171 160.421,98.171 160.548,98.298 v1(160.655,98.298) ; J1.18 159.691,100.574 160.137,100.574 160.147,100.584 v1(160.528,100.584) ; J1.46 162.307,94.713 163.097,94.713 v1(163.195,94.615) ; J1.47 162.292,109.375 163.09,109.375 v1(163.114,109.398) ; J1.13 162.567,99.028 163.367,99.028 v1(163.392,99.003)
LEDA2: J1.8 R7.1 | length 4.7
  L1 w0.254: J1.8 159.691,97.528 160.084,97.528 160.32,97.292 160.32,94.555 160.32,93.345 R7.1@160.317,93.342
LEDC2: J1.7 R7.2 | length 5.8
  L1 w0.254: R7.2@161.516,93.345 161.516,93.296 161.467,93.345 161.467,96.586 162.109,97.228 162.727,97.228 162.773,97.274 163.401,97.274 163.536,97.409 v1(163.576,97.409)
NetC6_2: C6.2 U1.1 | length 5
  L1 w0.254: C6.2@142.025,102.33 142.563,102.33 C6.2 145.127,102.388 145.276,102.239 U1.1 ; C6.2@142.025,102.422 142.341,102.738 142.341,102.87
NetC7_2: C7.2 U1.24 | length 2.9
  L1 w0.254: C7.2@143.586,105.125 143.598,105.136 145.127,105.136 145.276,105.285 U1.24
NetCVBS_1: CVBS.1 J4.2 R1.2 | length 8.8
  L1 w0.254: J4.2 136.526,90.127 138.485,90.127 R1.2
NetLED1_2: LED1.2 R6.1 | length 1.7
  L1 w0.254: R6.1 144.903,116.975 146.625,116.975 LED1.2
NetR1_1: R1.1 R5.2 U2.6 | length 12.4
  L1 w0.254: R1.1 146.812,85.471 149.626,88.285 149.626,88.529 149.794,88.697 U2.6@149.881,88.697 ; R5.2 148.959,89.661 149.623,88.996 149.623,88.865 149.791,88.697 150.292,88.697 U2.6
NetR2_2: R2.2 U1.23 | length 5.1
  L1 w0.254: R2.2 143.129,106.68 144.066,107.617 145.735,107.617 145.883,107.468 145.883,106.497 U1.23
NetR3_2: R3.2 R5.1 U2.2 | length 5.8
  L1 w0.254: U2.2 146.221,89.967 147.32,91.066 R5.1@147.32,93.218 ; R3.2 147.447,93.357 R5.1
NetR4_2: R4.2 U1.2 U2.3 | length 15.2
  L1 w0.254: U2.3 144.118,88.697 143.51,89.305 143.51,94.107 145.911,96.508 U1.2
NetR6_2: R6.2 S4.2 U1.6 | length 24.3
  L1 w0.254: S4.2 ccw(c143.69,120.387) 143.256,120.387 v1(143.256,119.126) 143.256,118.251 143.256,116.975 143.387,116.975 R6.2 ; U1.6 148.457,101.206 148.457,102.483 v1(148.463,102.489)
  L4 w0.254: v1(143.256,119.126) 143.256,107.188 147.955,102.489 v1(148.463,102.489)
P10: J1.25 S1.1 | length 23.1
  L1 w0.254: S1.1 157.25,122.404 161.417,118.237 161.417,103.366 162.109,102.674 162.521,102.674 J1.25
P11: J1.24 S2.1 | length 13.6
  L1 w0.254: S2.1 157.504,113.006 160.401,110.109 160.401,102.523 160.252,102.374 159.691,102.374 J1.24
P12: J1.23 S3.1 | length 19.3
  L1 w0.254: S3.1 157.885,117.705 160.909,114.681 160.909,103.232 162.067,102.074 162.521,102.074 J1.23
SG: J1.3 J1.4 J2.1 J3.1 SG.1 | length 6.3
  L1 w0.254: v1(158.824,96.32) 158.839,96.336 159.653,96.336 J1.4 ; J1.3 162.549,96.056 163.327,96.056 v1(163.334,96.049)
  L4 w0.254: v1(158.824,96.32) 161.04,96.32 161.311,96.049 v1(163.334,96.049)
SHD: pad.3 T2.1 | length 118
  L1 w0.5: T2.1 T2.1@128.362,119.38 ; pad.3@130.862,122.692 130.055,121.885 128.362,121.885 T2.1@128.362,119.38 ; pad.3@131.205,123.499 131.669,123.499 131.669,125.192 161.701,125.192 162.862,124.031 pad.3@162.862,122.692 ; pad.3@162.862,79.692 161.905,78.735 161.905,77.196 161.901,77.192 131.596,77.192 131.596,78.958 130.862,79.692 129.509,79.692 128.362,80.839 T2.1@128.362,119.38
SPLO: J1.1 J1.2 J2.2 SPLO.1 | length 7
  L1 w0.254: v1(158.872,95.504) 159.096,95.728 159.645,95.728 J1.2 ; J1.1 162.561,95.434 163.448,95.434 163.595,95.286 v1(163.702,95.286)
  L4 w0.254: v1(158.872,95.504) 159.09,95.286 v1(163.702,95.286)
SPRO: J1.5 J1.6 J3.2 SPRO.1 | length 8.3
  L1 w0.254: v1@158.623,97.041 158.703,96.961 159.658,96.961 J1.6 ; v1@158.623,97.042 v1(158.623,97.155) ; J1.5 163.961,96.651 v1(164.02,96.711)
  L4 w0.254: v1(158.623,97.155) 160.775,97.155 161.156,96.774 163.957,96.774 v1(164.02,96.711)
TVCLK: J1.26 TVCLK.1 U1.9 | length 11.4
  L1 w0.254: U1.9 150.356,103.102 150.505,103.251 153.861,103.251 154.16,102.951 J1.26
TVDATA0: J1.37 TVD0.1 U1.11 | length 20.8
  L1 w0.254: U1.11 151.632,101.206 151.632,102.395 v1(151.638,102.401) ; J1.37 163.655,106.251 v1(163.703,106.299)
  L4 w0.254: v1(151.638,102.401) 152.439,101.6 164.338,101.6 164.846,102.108 164.846,105.156 v1(163.703,106.299)
TVDATA1: J1.36 TVD1.1 U1.12 | length 22.8
  L1 w0.254: U1.12 152.339,101.278 152.339,102.196 152.527,102.384 v1(152.527,102.424) ; v1(158.75,105.824) 158.857,105.824 158.962,105.929 159.646,105.929 J1.36
  L4 w0.254: v1(152.527,102.424) 152.527,102.743 152.146,103.124 TVD1.1 148.336,103.124 146.271,105.189 146.271,105.399 146.79,105.918 158.656,105.918 v1(158.75,105.824)
TVDATA2: J1.35 TVD2.1 U1.13 | length 17.9
  L1 w0.254: v1(152.232,107.737) 152.261,107.708 U1.13 ; J1.35 164.314,105.651 164.962,106.299 v1(164.973,106.299)
  L4 w0.254: v1(152.232,107.737) 152.699,108.204 TVD2.1 163.411,108.204 164.899,106.716 164.899,106.373 v1(164.973,106.299)
TVDATA3: J1.34 TVD3.1 U1.14 | length 9.5
  L1 w0.254: U1.14 151.704,106.392 151.704,105.64 152.122,105.222 154.94,105.222 ; TVD3.1 154.94,105.222 ; J1.34 159.493,105.351 159.364,105.222 154.94,105.222
TVDATA4: J1.33 TVD4.1 U1.15 | length 15.8
  L1 w0.254: U1.15 151.01,106.489 151.01,107.476 151.257,107.723 v1(151.257,107.773) ; J1.33 162.566,105.029 v1(163.322,105.029)
  L4 w0.254: v1(151.257,107.773) 151.307,107.773 152.113,106.967 155.321,106.967 ; TVD4.1 155.321,106.967 ; v1(163.322,105.029) 162.306,105.029 160.368,106.967 155.321,106.967
TVDATA5: J1.32 TVD5.1 U1.16 | length 12.7
  L1 w0.254: TVD5.1@150.434,108.458 150.434,106.548 U1.16 150.368,106.458 150.368,105.41 151.027,104.751 J1.32
TVDATA6: J1.31 TVD6.1 U1.17 | length 18.1
  L1 w0.254: v1(149.702,107.699) 149.727,107.674 149.727,106.476 U1.17 ; J1.31 162.546,104.453 163.047,104.453 163.073,104.427 163.797,104.427 v1(163.83,104.394)
  L4 w0.254: v1(149.702,107.699) 149.702,107.594 150.492,106.804 TVD6.1 150.876,106.426 160.02,106.426 162.019,104.427 163.797,104.427 v1(163.83,104.394)
TVDATA7: J1.30 TVD7.1 U1.18 | length 12.5
  L1 w0.254: U1.18 149.098,106.458 149.098,104.902 149.86,104.14 155.326,104.14 TVD7.1 155.439,104.173 155.7,104.173 155.705,104.178 159.346,104.178 159.35,104.174 159.47,104.174 159.493,104.151 J1.30
TVDATA8: J1.29 TVD8.1 U1.19 | length 19.2
  L1 w0.254: U1.19 148.478,106.442 v1(148.478,104.917) ; J1.29 162.531,103.864 163.508,103.864 163.868,103.505 v1(163.957,103.505)
  L4 w0.254: v1(148.478,104.917) 158.445,104.917 158.51,104.853 158.926,104.853 160.188,103.591 163.871,103.591 v1(163.957,103.505)
TVDATA9: J1.27 TVD9.1 U1.20 | length 19.5
  L1 w0.254: v1(147.447,105.029) 147.816,105.398 U1.20 ; J1.27 163.08,103.251 v1(163.419,102.912)
  L4 w0.254: v1(147.447,105.029) 148.209,104.267 157.48,104.267 158.835,102.912 160.02,102.912 v1(163.419,102.912)
pads on no net: J1.9 J1.11 J1.12 J1.14 J1.15 J1.16 J1.17 J1.19 J1.20 J1.21 J1.22 J1.38 J1.39 J1.40 J1.44 J1.45 S4. U1.3 U1.8 U2.1 U2.5 U2.8

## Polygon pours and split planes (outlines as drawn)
SPLO on L4 "SPLO_L04_P004" (solid, pour order 4): 134.493,101.981 134.493,99.568 142.748,91.313 155.829,91.313 159.639,95.123 159.639,95.818 158.302,95.818 156.21,93.726 144.018,93.726 138.049,99.695 138.049,101.981
SG on L4 "SG_L04_P003" (solid, pour order 3): 129.921,115.951 133.731,115.951 133.731,99.441 143.383,89.789 162.052,89.789 164.084,91.821 164.084,95.758 163.068,95.758 163.068,96.393 165.608,96.393 165.608,89.281 163.195,86.868 142.367,86.868 129.921,99.314
SPRO on L4 "SPRO_L04_P005" (solid, pour order 5): 134.493,114.173 134.493,107.188 138.938,102.743 138.938,99.568 144.272,94.234 156.146,94.234 159.004,97.092 159.004,97.536 157.353,97.536 156.337,96.52 145.923,96.52 141.859,100.584 141.859,104.267 137.922,108.204 137.922,114.173
no net on L4 "NONET_L04_P002" (solid, pour order 2): 129.667,116.84
+3.3V on L3-PW "+3.3V_L03_P001" (solid, pour order 1): 142.113,116.459 146.159,120.505 147.982,120.505 147.982,113.257 153.543,107.696 153.543,98.171 146.538,91.166 146.538,86.888 153.035,86.888 159.766,93.619 159.766,105.814 161.721,107.769 163.582,107.784 163.488,89.447 157.226,83.185 143.751,83.198 142.113,84.836
no net on Board "NONET_L-01_P-001" (none): 127.855,79.692 cw(c127.862,79.692)
AGND on L1 "AGND_L01_P000" (solid, pour order 0): 141.243,108.331 141.243,97.825 144.98,97.825 144.992,96.51 141.681,93.199 141.681,90.043 139.7,90.043 139.7,93.199 134.112,93.199 134.098,88.152 137.668,84.582 150.622,84.582 154.559,88.519 154.559,94.234 145.542,94.234 145.551,95.448 146.826,96.723 155.245,96.723 156.972,94.996 156.972,86.995 152.123,82.146 136.676,82.145 133.757,85.064 129.667,85.064 129.667,95.504 139.446,95.504 139.446,108.331
GND on L2-GND (split plane): 130.862,125.182 162.862,125.182 162.878,125.183 163.079,125.174 163.295,125.146 163.507,125.099 163.714,125.034 163.915,124.95 164.108,124.85 164.291,124.733 164.464,124.601 164.624,124.454 164.771,124.294 164.903,124.121 165.02,123.938 165.12,123.745 165.204,123.544 165.269,123.337 165.316,123.125 165.344,122.909 165.353,122.708 165.352,122.692 165.352,79.692 165.353,79.676 165.344,79.475 165.316,79.259 165.269,79.047 165.204,78.84 165.12,78.639 165.02,78.446 164.903,78.263 164.771,78.09 164.624,77.93 164.464,77.783 164.291,77.651 164.108,77.534 163.915,77.434 163.714,77.35 163.507,77.285 163.295,77.238 163.079,77.21 162.878,77.201 162.862,77.202 130.862,77.202 130.846,77.201 130.645,77.21 130.429,77.238 130.217,77.285 130.01,77.35 129.809,77.434 129.616,77.534 129.433,77.651 129.26,77.783 129.1,77.93 128.953,78.09 128.821,78.263 128.704,78.446 128.604,78.639 128.52,78.84 128.455,79.047 128.408,79.259 128.38,79.475 128.371,79.676 128.372,79.692 128.372,122.692 128.371,122.708 128.38,122.909 128.408,123.125 128.455,123.337 128.52,123.544 128.604,123.745 128.704,123.938 128.821,124.121 128.953,124.294 129.1,124.454 129.26,124.601 129.433,124.733 129.616,124.85 129.809,124.95 130.01,125.034 130.217,125.099 130.429,125.146 130.645,125.174 130.846,125.183

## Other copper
L2-GND (plane layer: these items are gaps in the copper):
  lines w1.016: 130.862,125.692 ccw(c130.862,122.692) 127.862,122.692 127.862,79.692 ccw(c130.862,79.692) 130.862,76.692 162.862,76.692 ccw(c162.862,79.692) 165.862,79.692 165.862,122.692 ccw(c162.862,122.692) 162.862,125.692 130.862,125.692 ; 130.862,125.692 130.862,125.692

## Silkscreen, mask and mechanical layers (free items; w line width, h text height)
Top Overlay:
  text "'.Company'" at 151.003,78.232 h2
  text "'.Project' '.VersionRevision'" at 134.874,78.105 h2
Bottom Overlay:
  text "'.Company'  '.Year'" at 150.876,78.994 h2
Board:
  the board outline again, w0.013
